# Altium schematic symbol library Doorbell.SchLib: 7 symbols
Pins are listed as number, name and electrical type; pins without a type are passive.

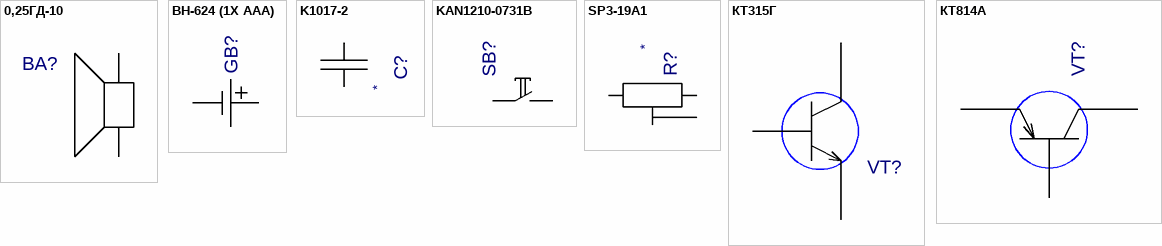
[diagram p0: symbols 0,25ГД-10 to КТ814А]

## 0,25ГД-10
designator BA?  (value not drawn)
footprint 0,25ГД-10
pins: 1, 2, 3 hidden, 4 hidden, 5 hidden, 6 hidden

## BH-624 (1X AAA)
designator GB?  (value not drawn)
footprint BH-624 (1X AAA)
pins: 1, 2

## K1017-2
designator C?  (value not drawn)
footprint K1017-2
pins: 1 I/OA, 2 I/OB

## KAN1210-0731B
designator SB?  (value not drawn)
footprint KAN1210-0731B
pins: 1, 2 hidden, 3 2, 4 hidden

## SP3-19A1
designator R?  (value not drawn)
footprint SP3-19A1
pins: 1 I/O1, 2 I/O2, 3 I/O3

## КТ315Г
designator VT?  (value not drawn)
footprint KT13
pins: 1 E, 2 B, 3 K

## КТ814А
designator VT?  (value not drawn)
footprint KT-27
pins: 1 E, 2 K, 3 B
